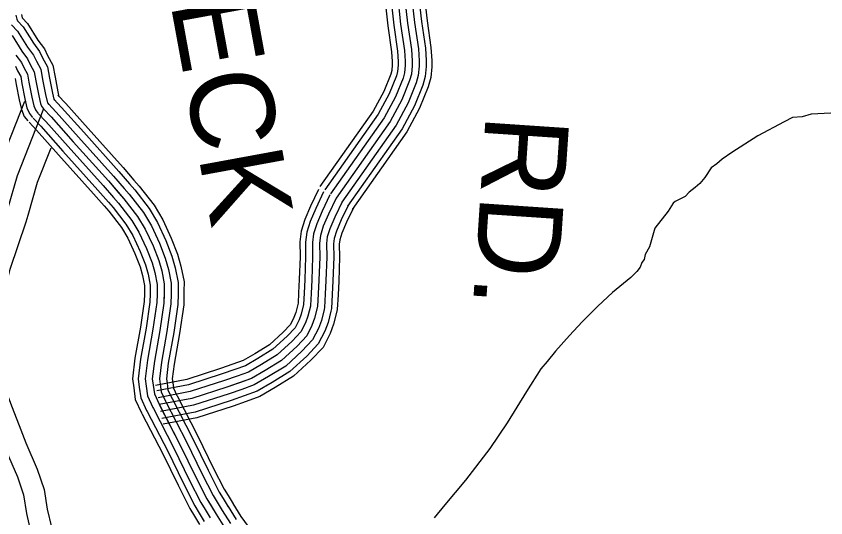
# Model space of a CAD drawing. Extents: x 1551132 to 1791609, y 378168 to 563823.
# Drawn here: x 1601513 to 1605092, y 413073 to 415289 of the extents above; entities that cross this region are included whole.
import ezdxf

# ---------------------------------------------------------------- set-up
doc = ezdxf.new("R2010")
doc.units = 0
for name, color, linetype in [('DESIGN - ROW - Right-of-Way and Easement Labels', 7, 'Continuous'), ('DESIGN - TRANSPORTATION - Text', 7, 'Continuous'), ('SURVEY - PROPERTY - Owners', 7, 'Continuous'), ('SURVEY - TRANSPORTATION - Roads', 7, 'Continuous')]:
    doc.layers.add(name, color=color, linetype=linetype)

msp = doc.modelspace()

# ---------------------------------------------------------------- linework, layer by layer
at = {"layer": 'DESIGN - TRANSPORTATION - Text'}
msp.add_lwpolyline([(1605115.212, 414860.96), (1605027.198, 414856.318), (1604987.049, 414844.909), (1604945.016, 414841.559), (1604908.742, 414822.083), (1604791.853, 414759.773), (1604676.806, 414687.421), (1604634.373, 414658.021), (1604610.057, 414636.353), (1604585.8, 414618.703), (1604557.167, 414577.068), (1604534.759, 414549.359), (1604514.493, 414531.642), (1604488.21, 414512.017), (1604469.91, 414492.258), (1604449.778, 414482.558), (1604426.528, 414469.957), (1604417.495, 414463.015), (1604394.954, 414427.298), (1604335.822, 414352.079), (1604312.572, 414270.285), (1604294.064, 414236.509), (1604289.723, 414214.542), (1604279.515, 414200.675), (1604271.215, 414180.766), (1604256.915, 414160.949), (1604230.533, 414135.307), (1604149.551, 414068.438), (1604084.644, 414007.328), (1604015.621, 413938.276), (1603958.739, 413879.041), (1603897.707, 413809.865), (1603861.024, 413764.347), (1603832.525, 413730.721), (1603769.026, 413631.526), (1603682.928, 413492.606), (1603607.23, 413379.57), (1603499.116, 413238.983), (1603407.493, 413130.196), (1603360.636, 413072.82)], dxfattribs=at)
at = {"layer": 'SURVEY - PROPERTY - Owners'}
for points in [[(1603229.023, 415388.172), (1603243.523, 415257.627), (1603260.189, 415141.099), (1603263.614, 415090.915), (1603263.539, 415069.206), (1603260.189, 415032.771), (1603252.598, 415004.787), (1603217.548, 414918.935), (1603166.366, 414823.241), (1602927.797, 414485.748)], [(1601549.812, 414912.684), (1601431.223, 414613.284), (1601388.266, 414463.239), (1601379.749, 414437.663), (1601308.234, 414222.907), (1601273.018, 414086.545), (1601245.877, 413962.617), (1601243.044, 413938.075), (1601238.319, 413897.174), (1601231.894, 413829.688), (1601241.119, 413752.345), (1601249.394, 413714.427), (1601261.943, 413653.417), (1601320.325, 413501.355), (1601353.608, 413414.569), (1601384.449, 413334.167), (1601433.956, 413220.756), (1601456.93, 413153.321), (1601468.996, 413075.185), (1601487.779, 412996.717), (1601493.896, 412957.341), (1601509.17, 412858.83), (1601540.578, 412681.083)], [(1601634.144, 414879.275), (1601517.196, 414584.025), (1601474.939, 414436.413), (1601395.282, 414197.207), (1601361.266, 414065.495), (1601335.459, 413947.675), (1601328.534, 413887.673), (1601323.117, 413830.772), (1601330.667, 413767.429), (1601338.133, 413733.244), (1601349.291, 413678.976), (1601405.007, 413533.856), (1601468.405, 413368.576), (1601518.595, 413253.59), (1601545.361, 413175.038), (1601558.078, 413092.694), (1601576.852, 413014.259), (1601598.66, 412873.672), (1601629.901, 412696.867)], [(1601666.885, 414706.487), (1601606.569, 414553.616), (1601565.037, 414408.529), (1601555.27, 414379.211), (1601485.763, 414170.489), (1601452.997, 414043.611), (1601428.581, 413932.141), (1601426.815, 413916.866), (1601422.306, 413877.798), (1601417.94, 413831.897), (1601423.756, 413783.104), (1601430.373, 413752.803), (1601440.089, 413705.552), (1601493.038, 413567.64), (1601526.329, 413480.838), (1601555.678, 413404.344), (1601606.577, 413287.716), (1601637.284, 413197.614), (1601650.676, 413110.895), (1601669.442, 413032.493), (1601676.7, 412985.708), (1601691.683, 412889.106), (1601722.749, 412713.276)], [(1602927.797, 414485.748), (1602893.697, 414414.463), (1602870.881, 414360.712), (1602858.223, 414320.794), (1602853.748, 414286.843), (1602854.79, 414224.716), (1602851.206, 414122.589), (1602848.282, 414062.521), (1602845.415, 414006.469)], [(1602845.415, 414006.469), (1602832.623, 413954.568), (1602820.499, 413922.359), (1602797.441, 413876.974), (1602754.767, 413831.548), (1602685.835, 413768.504), (1602613.178, 413723.545), (1602552.672, 413688.411), (1602444.149, 413650.018), (1602289.478, 413600.316), (1602145.914, 413573.049)], [(1602397.5, 413089.72), (1602434.574, 413031.043)]]:
    msp.add_lwpolyline(points, dxfattribs=at)
at = {"layer": 'SURVEY - TRANSPORTATION - Roads'}
for points in [[(1603290.739, 415394.123), (1603305.038, 415265.444), (1603321.888, 415147.608), (1603325.621, 415092.923), (1603325.529, 415066.256), (1603321.438, 415021.729), (1603311.438, 414984.878), (1603273.73, 414892.526), (1603219.215, 414790.598), (1602978.42, 414449.956)], [(1603315.346, 415396.498), (1603329.554, 415268.553), (1603346.487, 415150.199), (1603350.337, 415093.723), (1603350.237, 415065.081), (1603345.854, 415017.329), (1603334.896, 414976.945), (1603296.13, 414882.001), (1603240.289, 414777.581), (1602998.603, 414435.689)], [(1603141.709, 415379.747), (1603156.5, 415246.569), (1603172.9, 415131.891), (1603175.891, 415088.073), (1603175.841, 415073.381), (1603173.541, 415048.388), (1603169.35, 415032.955), (1603138.059, 414956.303), (1603091.593, 414869.425), (1602856.173, 414536.383)], [(1603167.308, 415382.222), (1603182.008, 415249.81), (1603198.491, 415134.591), (1603201.607, 415088.906), (1603201.549, 415072.156), (1603198.941, 415043.813), (1603193.757, 415024.696), (1603161.366, 414945.344), (1603113.517, 414855.883), (1602877.173, 414521.541)], [(1603198.166, 415385.197), (1603212.765, 415253.719), (1603229.34, 415137.841), (1603232.615, 415089.914), (1603232.548, 415070.681), (1603229.565, 415038.288), (1603223.182, 415014.746), (1603189.457, 414932.144), (1603139.942, 414839.558), (1602902.481, 414503.641)], [(1603229.023, 415388.172), (1603243.523, 415257.627), (1603260.189, 415141.099), (1603263.614, 415090.915), (1603263.539, 415069.206), (1603260.189, 415032.771), (1603252.598, 415004.787), (1603217.548, 414918.935), (1603166.366, 414823.241), (1602927.797, 414485.748)], [(1603229.023, 415388.172), (1603243.523, 415257.627), (1603260.189, 415141.099), (1603263.614, 415090.915), (1603263.539, 415069.206), (1603260.189, 415032.771), (1603252.598, 415004.787), (1603217.548, 414918.935), (1603166.366, 414823.241), (1602927.797, 414485.748)], [(1603259.881, 415391.147), (1603274.281, 415261.536), (1603291.038, 415144.358), (1603294.613, 415091.915), (1603294.53, 415067.731), (1603290.813, 415027.255), (1603282.014, 414994.829), (1603245.639, 414905.726), (1603192.791, 414806.924), (1602953.113, 414467.856)], [(1601512.222, 415293.502), (1601515.547, 415275.41), (1601518.372, 415268.293), (1601543.921, 415241.876), (1601589.02, 415169.591), (1601616.519, 415132.365), (1601630.027, 415104.197), (1601651.468, 415064.546), (1601660.552, 415015.045), (1601673.36, 414949.41), (1601679.293, 414922.376), (1601682.493, 414918.284)], [(1601536.98, 415295.561), (1601539.413, 415282.268), (1601539.538, 415281.968), (1601563.512, 415257.185), (1601609.478, 415183.499), (1601637.794, 415145.165), (1601652.052, 415115.431), (1601675.076, 415072.863), (1601684.843, 415019.637), (1601697.559, 414954.427), (1601702.226, 414933.176)], [(1601491.831, 415251.151), (1601519.363, 415222.684), (1601563.362, 415152.148), (1601589.845, 415116.306), (1601602.403, 415090.113), (1601621.869, 415054.121), (1601630.094, 415009.278), (1601643.002, 414943.11), (1601649.718, 414912.509), (1601652.21, 414906.684), (1601658.085, 414899.175)], [(1601494.797, 415203.491), (1601537.705, 415134.706), (1601563.162, 415100.247), (1601574.779, 415076.03), (1601592.262, 415043.696), (1601599.636, 415003.511), (1601612.644, 414936.818), (1601620.069, 414903.017), (1601625.294, 414890.775), (1601633.677, 414880.066)], [(1601494.797, 415203.491), (1601537.705, 415134.706), (1601563.162, 415100.247), (1601574.779, 415076.03), (1601592.262, 415043.696), (1601599.636, 415003.511), (1601612.644, 414936.818), (1601620.069, 414903.017), (1601625.294, 414890.775), (1601633.677, 414880.066)], [(1601512.047, 415117.264), (1601536.48, 415084.188), (1601547.154, 415061.946), (1601562.654, 415033.27), (1601569.179, 414997.744), (1601582.287, 414930.526), (1601590.42, 414893.525), (1601598.378, 414874.866), (1601609.269, 414860.957)], [(1601509.805, 415068.13), (1601519.53, 415047.862), (1601533.055, 415022.845), (1601538.721, 414991.978), (1601551.929, 414924.226), (1601560.762, 414884.033), (1601571.462, 414858.957), (1601584.862, 414841.849)], [(1601508.497, 415014.195), (1601513.447, 414987.194), (1601526.746, 414919.009), (1601536.163, 414876.158), (1601549.137, 414845.757), (1601564.612, 414825.99)], [(1601697.834, 414939.876), (1601731.883, 414903.35), (1601830.656, 414793.039), (1601986.344, 414619.826), (1602033.668, 414565.275)], [(1601656.352, 414901.209), (1601690.009, 414865.091), (1601788.44, 414755.163), (1601943.828, 414582.284), (1601990.835, 414528.107)], [(1601679.026, 414922.342), (1601712.9, 414886.008), (1601811.515, 414775.864), (1601967.069, 414602.801), (1602014.251, 414548.424)], [(1601611.003, 414858.924), (1601644.243, 414823.273), (1601742.291, 414713.762), (1601897.362, 414541.233), (1601944.003, 414487.473)], [(1601633.677, 414880.066), (1601667.126, 414844.182), (1601765.366, 414734.463), (1601920.595, 414561.758), (1601989.327, 414482.548), (1602049.859, 414404.554), (1602083.2, 414348.861), (1602118.015, 414274.184), (1602143.006, 414209.682), (1602156.281, 414163.389), (1602167.397, 414107.121), (1602166.906, 414075.07), (1602166.064, 414020.986), (1602148.223, 413901.041), (1602124.132, 413765.171), (1602114.932, 413687.169), (1602118.498, 413659.059), (1602123.898, 413620.908), (1602145.164, 413574.499), (1602238.329, 413394.736), (1602306.127, 413255.432), (1602356.559, 413156.48), (1602397.5, 413089.72)], [(1601633.677, 414880.066), (1601667.126, 414844.182), (1601765.366, 414734.463), (1601920.595, 414561.758), (1601989.327, 414482.548), (1602049.859, 414404.554), (1602083.2, 414348.861), (1602118.015, 414274.184), (1602143.006, 414209.682), (1602156.281, 414163.389), (1602167.397, 414107.121), (1602166.906, 414075.07), (1602166.064, 414020.986), (1602148.223, 413901.041), (1602124.132, 413765.171), (1602114.932, 413687.169), (1602118.498, 413659.059), (1602123.898, 413620.908), (1602145.164, 413574.499), (1602238.329, 413394.736), (1602306.127, 413255.432), (1602356.559, 413156.48), (1602397.5, 413089.72)], [(1601633.677, 414880.066), (1601667.126, 414844.182), (1601765.366, 414734.463), (1601920.595, 414561.758), (1601967.419, 414507.79)], [(1601570.245, 414820.931), (1601603.103, 414785.689), (1601700.817, 414676.553), (1601855.597, 414504.348), (1601901.921, 414450.955)], [(1601588.328, 414837.79), (1601621.352, 414802.356), (1601719.217, 414693.061), (1601874.121, 414520.715), (1601920.587, 414467.156)], [(1602014.235, 414548.441), (1602037.267, 414521.899), (1602101.133, 414439.613), (1602138.04, 414377.962), (1602175.081, 414298.51), (1602201.83, 414229.466), (1602216.596, 414177.973), (1602229.488, 414112.713), (1602228.896, 414074.112), (1602228.679, 414060.303)], [(1602033.659, 414565.292), (1602057.15, 414538.224), (1602122.399, 414454.155), (1602160.781, 414390.037), (1602198.747, 414308.602), (1602226.23, 414237.675), (1602241.612, 414184.015), (1602255.245, 414115.038), (1602254.612, 414073.712), (1602254.395, 414059.903)], [(1601967.411, 414507.807), (1601989.327, 414482.548), (1602049.859, 414404.554), (1602083.2, 414348.861), (1602118.015, 414274.184), (1602143.006, 414209.682), (1602156.281, 414163.389), (1602167.397, 414107.121), (1602166.906, 414075.07), (1602166.689, 414061.278)], [(1601990.827, 414528.124), (1602013.293, 414502.223), (1602075.491, 414422.08), (1602110.616, 414363.411), (1602146.548, 414286.351), (1602172.414, 414219.574), (1602186.439, 414170.681), (1602198.447, 414109.921), (1602197.905, 414074.587), (1602197.688, 414060.795)], [(1602849.573, 414523.174), (1602814.633, 414450.131), (1602789.458, 414390.829), (1602773.25, 414339.711), (1602766.942, 414291.81), (1602768.05, 414225.508), (1602764.567, 414126.222), (1602761.675, 414066.846), (1602759.234, 414019.186)], [(1602871.865, 414512.507), (1602837.174, 414439.964), (1602812.666, 414382.246), (1602797.475, 414334.319), (1602791.683, 414290.393), (1602792.775, 414225.283), (1602789.258, 414125.181), (1602786.358, 414065.612), (1602783.8, 414015.561)], [(1602899.831, 414499.124), (1602865.431, 414427.213), (1602841.774, 414371.479), (1602827.849, 414327.561), (1602822.716, 414288.618), (1602823.782, 414225), (1602820.232, 414123.889), (1602817.324, 414064.062), (1602814.607, 414011.011), (1602813.907, 414008.186)], [(1601920.587, 414467.172), (1601941.386, 414443.197), (1601998.585, 414369.495), (1602028.359, 414319.76), (1602060.95, 414249.858), (1602084.183, 414189.898), (1602095.966, 414148.806), (1602105.307, 414101.529), (1602104.916, 414076.029), (1602104.699, 414062.253)], [(1601943.995, 414487.49), (1601965.361, 414462.872), (1602024.226, 414387.029), (1602055.784, 414334.311), (1602089.483, 414262.017), (1602113.599, 414199.79), (1602126.123, 414156.098), (1602136.348, 414104.321), (1602135.907, 414075.554), (1602135.69, 414061.762)], [(1602927.797, 414485.748), (1602893.697, 414414.463), (1602870.881, 414360.712), (1602858.223, 414320.794), (1602853.748, 414286.843), (1602854.79, 414224.716), (1602851.206, 414122.589), (1602848.282, 414062.521), (1602845.415, 414006.469), (1602844.007, 414000.761)], [(1602927.797, 414485.748), (1602893.697, 414414.463), (1602870.881, 414360.712), (1602858.223, 414320.794), (1602853.748, 414286.843), (1602854.79, 414224.716), (1602851.206, 414122.589), (1602848.282, 414062.521), (1602845.415, 414006.469)], [(1602955.763, 414472.373), (1602921.963, 414401.713), (1602899.989, 414349.945), (1602888.597, 414314.027), (1602884.781, 414285.068), (1602885.797, 414224.433), (1602882.181, 414121.289), (1602879.239, 414060.979), (1602876.222, 414001.927), (1602874.106, 413993.335)], [(1601901.912, 414450.972), (1601922.278, 414427.505), (1601978.144, 414355.519), (1602006.501, 414308.16), (1602038.201, 414240.158), (1602060.733, 414182.007), (1602071.916, 414142.997), (1602080.549, 414099.296), (1602080.199, 414076.42), (1602079.983, 414062.637)], [(1602983.729, 414458.989), (1602950.221, 414388.963), (1602929.096, 414339.178), (1602918.972, 414307.269), (1602915.813, 414283.293), (1602916.805, 414224.15), (1602913.155, 414119.997), (1602910.205, 414059.429), (1602907.03, 413997.377), (1602904.197, 413985.91)], [(1603006.92, 414447.897), (1602973.67, 414378.379), (1602953.238, 414330.244), (1602944.171, 414301.66), (1602941.563, 414281.818), (1602942.529, 414223.917), (1602938.846, 414118.914), (1602935.888, 414058.146), (1602932.588, 413993.61), (1602929.171, 413979.752)], [(1602079.983, 414062.637), (1602079.449, 414028.069), (1602062.633, 413914.991), (1602038.309, 413777.829), (1602027.567, 413686.785), (1602032.55, 413647.526), (1602039.808, 413596.258), (1602067.199, 413536.481), (1602069.991, 413531.089)], [(1602104.699, 414062.253), (1602104.141, 414026.052), (1602087.024, 413911.016), (1602062.775, 413774.221), (1602052.475, 413686.894), (1602057.05, 413650.809), (1602063.775, 413603.283), (1602089.424, 413547.315), (1602091.941, 413542.456)], [(1602135.69, 414061.778), (1602135.098, 414023.519), (1602117.624, 413906.033), (1602093.449, 413769.696), (1602083.699, 413687.027), (1602087.774, 413654.934), (1602093.841, 413612.1), (1602117.29, 413560.907), (1602119.465, 413556.707)], [(1602166.689, 414061.295), (1602166.064, 414020.986), (1602148.223, 413901.041), (1602124.132, 413765.171), (1602114.932, 413687.169), (1602118.498, 413659.059), (1602123.898, 413620.908), (1602145.164, 413574.499), (1602146.998, 413570.957)], [(1602197.688, 414060.812), (1602197.03, 414018.452), (1602178.822, 413896.049), (1602154.814, 413760.646), (1602146.164, 413687.31), (1602149.223, 413663.185), (1602153.956, 413629.717), (1602173.039, 413588.091), (1602174.53, 413585.208)], [(1602228.679, 414060.337), (1602227.988, 414015.919), (1602209.421, 413891.066), (1602185.488, 413756.12), (1602177.389, 413687.444), (1602179.947, 413667.31), (1602184.022, 413638.534), (1602200.905, 413601.683), (1602202.055, 413599.458)], [(1602254.395, 414059.937), (1602253.679, 414013.819), (1602234.804, 413886.924), (1602210.946, 413752.362), (1602203.296, 413687.56), (1602205.438, 413670.727), (1602208.955, 413645.843), (1602224.029, 413612.958), (1602224.896, 413611.283)], [(1602845.415, 414006.469), (1602832.623, 413954.568), (1602820.499, 413922.359), (1602797.441, 413876.974), (1602754.767, 413831.548), (1602685.835, 413768.504), (1602613.178, 413723.545), (1602552.672, 413688.411), (1602444.149, 413650.018), (1602289.478, 413600.316), (1602145.914, 413573.049)], [(1602759.817, 414021.536), (1602749.659, 413980.31), (1602741.026, 413957.384), (1602725.751, 413927.309), (1602693.818, 413893.324), (1602633.303, 413837.973), (1602568.588, 413797.93), (1602516.122, 413767.463), (1602471.015, 413751.504)], [(1602783.816, 414015.619), (1602773.308, 413972.976), (1602763.675, 413947.401), (1602746.184, 413912.967), (1602711.193, 413875.716), (1602648.278, 413818.172), (1602581.296, 413776.73), (1602526.539, 413744.929), (1602479.257, 413728.203)], [(1602813.916, 414008.194), (1602802.966, 413963.768), (1602792.091, 413934.876), (1602771.817, 413894.966), (1602732.976, 413853.632), (1602667.052, 413793.338), (1602597.237, 413750.137), (1602539.605, 413716.67), (1602489.598, 413698.977)], [(1602844.015, 414000.777), (1602832.623, 413954.568), (1602820.499, 413922.359), (1602797.441, 413876.974), (1602754.767, 413831.548), (1602685.835, 413768.504), (1602613.178, 413723.545), (1602552.672, 413688.411), (1602499.939, 413669.752)], [(1602874.114, 413993.36), (1602862.281, 413945.367), (1602848.906, 413909.842), (1602823.065, 413858.982), (1602776.558, 413809.464), (1602704.618, 413743.67), (1602629.12, 413696.952), (1602565.738, 413660.151), (1602510.281, 413640.526)], [(1602904.213, 413985.935), (1602891.939, 413936.159), (1602877.322, 413897.316), (1602848.698, 413840.981), (1602798.341, 413787.38), (1602723.393, 413718.836), (1602645.061, 413670.36), (1602578.804, 413631.892), (1602520.622, 413611.3)], [(1602929.18, 413979.777), (1602916.546, 413928.525), (1602900.888, 413886.933), (1602869.956, 413826.056), (1602816.415, 413769.063), (1602738.975, 413698.228), (1602658.286, 413648.301), (1602589.637, 413608.442), (1602529.197, 413587.058)], [(1602471.04, 413751.512), (1602416.416, 413732.195), (1602268.045, 413684.51), (1602129.731, 413658.243)], [(1602479.282, 413728.212), (1602424.325, 413708.769), (1602274.153, 413660.518), (1602134.348, 413633.959)], [(1602489.615, 413698.986), (1602434.233, 413679.394), (1602281.811, 413630.417), (1602140.131, 413603.508)], [(1602499.956, 413669.76), (1602444.149, 413650.018), (1602289.478, 413600.316), (1602145.914, 413573.049)], [(1602510.297, 413640.534), (1602454.065, 413620.642), (1602297.144, 413570.216), (1602151.697, 413542.59)], [(1602520.631, 413611.308), (1602463.974, 413591.266), (1602304.802, 413540.115), (1602157.481, 413512.139)], [(1602224.862, 413611.342), (1602316.71, 413434.12), (1602384.642, 413294.55), (1602433.141, 413199.389), (1602449.899, 413172.064)], [(1602146.989, 413570.974), (1602238.329, 413394.736), (1602306.127, 413255.432), (1602356.559, 413156.48), (1602375.125, 413126.204)], [(1602529.205, 413587.066), (1602472.198, 413566.891), (1602311.16, 413515.147), (1602162.281, 413486.872)], [(1602174.514, 413585.241), (1602266.028, 413408.653), (1602333.876, 413269.258), (1602383.625, 413171.647), (1602401.55, 413142.413)], [(1602202.03, 413599.508), (1602293.736, 413422.57), (1602361.626, 413283.083), (1602410.691, 413186.814), (1602427.974, 413158.622)], [(1602069.999, 413531.073), (1602160.839, 413355.802), (1602228.504, 413216.765), (1602280.853, 413114.054), (1602301.202, 413080.869)], [(1602091.949, 413542.44), (1602182.922, 413366.902), (1602250.628, 413227.782), (1602302.427, 413126.146), (1602322.277, 413093.786)], [(1602119.465, 413556.707), (1602210.629, 413380.819), (1602278.378, 413241.607), (1602329.493, 413141.313), (1602348.701, 413109.995)], [(1602401.541, 413142.421), (1602423.924, 413105.928)], [(1602427.966, 413158.63), (1602450.349, 413122.137)], [(1602449.89, 413172.08), (1602472.273, 413135.588)], [(1602348.693, 413110.004), (1602371.075, 413073.511)], [(1602375.117, 413126.212), (1602397.5, 413089.72)], [(1602423.708, 413106.278), (1602460.257, 413048.435)], [(1602449.915, 413122.837), (1602485.939, 413065.827)], [(1602470.806, 413136.046), (1602506.414, 413079.686), (1602574.921, 412985.1)], [(1602301.202, 413080.869), (1602323.585, 413044.377)], [(1602322.268, 413093.795), (1602344.651, 413057.302)], [(1602397.5, 413089.72), (1602434.574, 413031.043)], [(1602397.5, 413089.72), (1602434.574, 413031.043)]]:
    msp.add_lwpolyline(points, dxfattribs=at)

# ---------------------------------------------------------------- texts
at = {"layer": 'DESIGN - ROW - Right-of-Way and Easement Labels'}
for s, height, rotation, p in [('SHEEPNECK', 370.009, 280.397431, (1601827.066, 417348.873)), ('RD.', 370.0097, 266.139847, (1603589.481, 414859.75))]:
    msp.add_text(s, height=height, rotation=rotation, dxfattribs=at).set_placement(p)

doc.saveas('drawing.dxf')
